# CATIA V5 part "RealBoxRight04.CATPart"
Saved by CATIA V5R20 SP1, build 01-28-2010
Part number: RealBoxRight
Bounding box of the stored display mesh (mm): x 0 to 3, y 0 to 192, z 0 to 76.5
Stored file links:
  C:\Users\elisf\Desktop\Elis\ENSINOFATEC\MAV5\DIP\Labirinto\RealBox\RealBoxRight04.CATPart
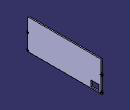
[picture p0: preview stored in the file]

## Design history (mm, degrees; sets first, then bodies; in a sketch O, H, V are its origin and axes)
Body1 (main body)
  Sketch1 on yz-plane, origin (0, 0, 0), H (0, 1, 0), V (0, 0, 1)
    line L1 (192, 0) -> (192, 6)
    line L2 (192, 6) -> (189, 6)
    line L3 (189, 6) -> (189, 39)
    line L4 (189, 39) -> (192, 39)
    point P5 (192, 39)
    line L5 (192, 39) -> (192, 45)
    line L6 (192, 45) -> (189, 45)
    point P7 (189, 45)
    line L7 (189, 45) -> (189, 76.5)
    line L8 (189, 76.5) -> (3, 76.5)
    line L9 (3, 76.5) -> (3, 45)
    point P10 (3, 45)
    line L10 (3, 45) -> (0, 45)
    line L11 (0, 45) -> (0, 39)
    point P12 (0, 39)
    line L12 (0, 39) -> (3, 39)
    point P13 (3, 39)
    line L13 (3, 39) -> (3, 6)
    point P14 (3, 6)
    line L14 (3, 6) -> (0, 6)
    point P15 (0, 6)
    line L15 (0, 6) -> (0, 0)
    point P16 (0, 0)
    line L16 (0, 0) -> (192, 0)
    length L1 = 6
    length L5 = 6
    length L2 = 3
    length L14 = 3
    distance L2 L4 = 33
    distance L3 L13 = 186
    distance L8 L16 = 76.5
    vertical: L1 V, L3 V, L5 V, L7 V, L9 V, L11 V, L13 V, L15 V
    horizontal: L2 H, L4 H, L6 H, L8 H, L10 H, L12 H, L14 H, L16 H
    coincidence: P5 L1, P7 L3, P10 L6, P12 L4, P13 L9, P14 L2, P15 L11, P16 H, P16 O
  Pad1: profile Sketch1, direction (1, 0, 0), length 3
  Sketch2 on end face of Pad1, origin (3, 0, 0), H (0, 1, 0), V (0, 0, 1)
    reference projected line E1 (192, 0) -> (192, 6) from edge [face of Pad1 from Sketch1.L1 | end face of Pad1]
    reference projected line E4 (192, 39) -> (192, 45) from edge [face of Pad1 from Sketch1.L5 | end face of Pad1]
    construction line L1 (192, 3) -> (189, 3)
    point P9 (192, 3)
    construction line L2 (192, 42) -> (189, 42)
    point P11 (192, 42)
    circle A1 centre (189, 42) radius 1.5
    circle A2 centre (189, 3) radius 1.5
    reference projected line E5 (0, 6) -> (0, 0) from edge [face of Pad1 from Sketch1.L15 | end face of Pad1]
    reference projected line E7 (0, 45) -> (0, 39) from edge [face of Pad1 from Sketch1.L11 | end face of Pad1]
    construction line L3 (0, 42) -> (3, 42)
    point P19 (0, 42)
    construction line L4 (0, 3) -> (3, 3)
    point P21 (0, 3)
    circle A3 centre (3, 42) radius 1.5
    circle A4 centre (3, 3) radius 1.5
    length L1 = 3
    length L2 = 3
    radius A1 = 1.5
    radius A2 = 1.5
    length L3 = 3
    length L4 = 3
    radius A3 = 1.5
    radius A4 = 1.5
    midpoint: P9 E1, P11 E4, P19 E7, P21 E5
    horizontal: L1 H, L2 H, L3 H, L4 H
  Pocket1: profile Sketch2, direction (-1, 0, 0), length 3
  Sketch3 on end face of Pad1, origin (3, 0, 0), H (0, 1, 0), V (0, 0, 1)
    reference projected circle E1 centre (189, 3) radius 1.5 from edge [end face of Pad1 | face of Pocket1 from Sketch2.A2]
    reference projected circle E2 centre (189, 42) radius 1.5 from edge [end face of Pad1 | face of Pocket1 from Sketch2.A1]
    reference projected circle E3 centre (3, 42) radius 1.5 from edge [end face of Pad1 | face of Pocket1 from Sketch2.A3]
    reference projected circle E4 centre (3, 3) radius 1.5 from edge [end face of Pad1 | face of Pocket1 from Sketch2.A4]
    circle A1 centre (3, 42) radius 2
    point P1 (3, 42)
    circle A2 centre (3, 3) radius 2
    point P2 (3, 3)
    circle A3 centre (189, 42) radius 2
    point P3 (189, 42)
    circle A4 centre (189, 3) radius 2
    point P4 (189, 3)
    radius A1 = 2
    radius A2 = 2
    radius A4 = 2
    radius A3 = 2
    concentricity: P1 E3, P2 E4, P3 E2, P4 E1
  Pocket2: profile Sketch3, direction (-1, 0, 0), length 1
  Sketch4 on end face of Pad1, origin (3, 0, 0), H (0, 1, 0), V (0, 0, 1)
    reference projected line E1 (0, 0) -> (192, 0) from edge [face of Pad1 from Sketch1.L16 | end face of Pad1]
    construction line L1 (184, 3) -> (184, 0)
    point P5 (184, 0)
    reference projected line E3 (192, 0) -> (192, 6) from edge [face of Pad1 from Sketch1.L1 | end face of Pad1]
    line L2 (184, 3) -> (164, 3)
    line L3 (164, 3) -> (164, 18)
    line L4 (164, 18) -> (184, 18)
    line L5 (184, 18) -> (184, 3)
    distance E3 L1 = 8
    length L1 = 3
    length L5 = 15
    length L2 = 20
    coincidence: P5 E1
    vertical: L1 V, L3 V, L5 V
    horizontal: L2 H, L4 H
  Pocket3: profile Sketch4, direction (-1, 0, 0), length 3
